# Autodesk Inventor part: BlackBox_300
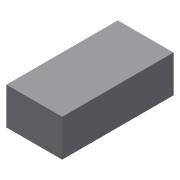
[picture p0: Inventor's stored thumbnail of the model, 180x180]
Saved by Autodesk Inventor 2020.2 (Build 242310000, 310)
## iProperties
Created: 2014-09
Part Number: BlackBox_300
Material: Ogólny
Document SubType Name: Modeling
Designer: F.Stasiak
Density: 1 g/cm^3
Appearance: Domyślna
Catalog Web Link: www.expertbooks.pl
Manager: www.cadconsulting.pl
Company: Fabian Stasiak CAD Consulting
Author: F.Stasiak
Subject: Zbiór ćwiczeń. Autodesk Inventor 2020. Kurs Professional
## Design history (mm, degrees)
sketch "Szkic1"
  geometry: L1 (0, 0)-(-60, 0); L2 (-60, 0)-(-60, 120); L3 (-60, 120)-(0, 120); L4 (0, 120)-(0, 0)
  constraints: 8 end point, 2 parallel, 1 horizontal, 1 perpendicular
  dimensions: "d0" = 60 distance of L2.end L3.end; "d1" = 120 distance of L1.end L2.end
extrude "Wyciągnięcie proste1" new body sketch "Szkic1" distance "d2" = 40; taper "d3" = 0 deg
node "Bryła1"
